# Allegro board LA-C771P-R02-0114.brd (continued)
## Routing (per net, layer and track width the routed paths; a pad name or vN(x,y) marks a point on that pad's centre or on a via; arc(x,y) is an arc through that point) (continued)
ICLK_RCOMP: length 2
  TOP w0.254: v3(108.64,84.84) 108.21,84.41 RC31.2
  BOTTOM w0.254: UC4.AD13 108.92,84.61 108.88,84.61 v3(108.64,84.84)
ICLK_USB_TERMN: length 4.7
  TOP w0.102: RC57.2 98.86,83.75 98.86,84.36 98.48,84.74 v4(98.48,85.05) 98.48,85.32 98.76,85.6 99.35,85.6 99.57,85.83 99.57,86.13 v3(99.75,86.3)
  BOTTOM w0.102: v3(99.75,86.3) 100.19,85.86 UC4.F10
ICLK_USB_TERMP: length 4.7
  TOP w0.102: v3(99.13,86.3) 99.35,86.08 99.35,85.93 99.25,85.83 98.67,85.83 98.25,85.42 98.25,84.64 98.63,84.26 98.63,83.8 RC56.2
  BOTTOM w0.102: v3(99.13,86.3) 99.48,85.95 UC4.D10
ILB_RTC_EXTPAD: length 7.6
  BOTTOM w0.102: CC17.1 94.39,91.4 v2(94.78,91.01) 96.14,89.65 96.14,87.92 97.44,86.62 98.34,86.62 UC4.B8
ILB_RTC_X1: length 11.4
  BOTTOM w0.102: YC2.2 91.19,90.3 CC19.1 93.35,90.3 RC42.2 94.01,89.65 94.34,89.65 v2(94.7,89.29) 95.01,88.98 95.01,86.76 95.85,85.91 97.98,85.91 98.12,86.06 98.21,86.15 UC4.C9
ILB_RTC_X2: length 11.1
  BOTTOM w0.102: UC4.A9 96.09,86.29 v2(95.54,86.84) 95.46,86.91 95.46,89.39 94.04,90.81 RC42.1 93.38,91.19 CC18.1 91.72,91.19 YC2.1
INVT_PWM_SOC: length 73.9
  TOP w0.102: RPC1.7 80.18,76.09 80.71,76.62 81.32,76.62 UC7.4 81.41,76.29 81.01,76.29 80.3,75.58 80.3,74.71 v1(79.04,73.45) 73.93,68.34 67.71,68.34 67.56,68.49 65.52,68.49 64.8,69.21 63.55,69.21 61.64,71.12 61.64,76.55 59.57,78.62 57.25,78.62 56.01,77.38 53.47,77.38 53.08,77.77 v3(53.08,79.27)
  IN1 w0.127: v3(53.08,79.27) 52.77,79.58 52.77,85.42 50.07,88.12 50.07,88.12 49.51,88.68 v3(49.51,95.57)
  BOTTOM w0.102: JEDP1.8 57.9,97.52 57.13,96.76 54.71,96.76 53.46,95.51 52.46,95.51 52.23,95.28 49.79,95.28 v3(49.51,95.57)
ISOLATE#: length 3.7
  BOTTOM w0.102: UL1.20 38.7,68.95 v2(38.99,69.24) 39.26,69.51 RL3.1 40.14,68.53 RL2.2
KSI0: length 101.8
  TOP w0.102: UB1.55 65.05,17.37 65.33,17.66 v3(65.33,18.83) ; v3(51.47,57.51) 51.47,57.54 50.73,56.8 49.08,56.8 44,61.89 44,69.22 44.38,69.61 44.38,72.32 44.79,72.72 44.79,76.28 53.15,84.64 57.49,84.64 57.72,84.87 ; 57.72,84.87 59.65,86.8 JKB1.12 59.65,87.77 60.26,88.38 60.26,90.38 63.9,94.02 JKB2.12 ; 57.72,84.87 v1(57.72,84.87)
  IN2 w0.127: v3(51.47,57.51) 50.48,56.52 50.48,52.4 51.42,51.46 51.42,43.08 52.97,41.53 52.97,29.82 63.96,18.83 v3(65.33,18.83)
KSI1: length 117.9
  TOP w0.102: v3(56.29,55.15) 54.76,56.68 54.76,57.29 54.76,57.29 54.76,57.72 52.35,60.13 v1(50.72,60.13) 50.21,60.13 46.51,63.83 46.51,67.89 46.9,68.28 46.9,71 51.47,75.57 51.47,78.56 55.04,82.12 60.94,82.12 63.78,84.97 65.66,84.97 66.35,85.66 69.3,85.66 70.65,87.01 JKB1.1 70.65,87.96 70.11,88.5 68.47,88.5 67.62,89.35 67.62,91.44 68.01,91.83 73.58,91.83 73.92,92.17 73.92,92.49 74.9,93.47 JKB2.1 ; v3(68.99,20.05) 68.69,20.05 67.27,18.62 67.27,17.99 66.24,16.97 UB1.56
  IN2 w0.127: v3(56.29,55.15) 57.22,55.15 60.79,51.58 60.79,43.44 60.23,42.88 60.23,37.28 60.99,36.52 60.99,30.72 64.12,27.59 64.12,25.49 65.57,24.03 66.65,24.03 68.99,21.69 v3(68.99,20.05)
KSI2: length 104.8
  TOP w0.102: UB1.57 62.36,16.57 58.76,20.18 58.76,23.02 55.61,26.17 55.61,31.26 57.54,33.19 57.54,34.35 57.81,34.62 v3(57.81,34.63) ; v3(52.84,55.81) 52.84,57.38 51.82,58.4 49.64,58.4 44.91,63.13 44.91,68.85 45.3,69.23 45.3,71.94 45.7,72.34 45.7,75.9 53.53,83.72 60.27,83.72 63.65,87.1 JKB1.8 63.65,88.21 62.95,88.91 62.95,90.04 66.14,93.23 67.15,93.23 67.9,93.98 JKB2.8
  IN2 w0.127: v3(52.84,55.81) 53.22,55.81 55.58,53.45 55.58,45.6 56.93,44.25 56.93,36.72 57.31,36.33 57.31,35.12 57.81,34.62 v3(57.81,34.63)
KSI3: length 105.9
  TOP w0.102: UB1.58 62.13,16.17 v2(58.73,19.57) 58.48,19.82 58.48,22.97 55.38,26.07 55.38,31.36 57.31,33.29 57.31,34.82 v3(57.76,35.28) ; JKB2.9 66.9,93.6 66.78,93.48 66.07,93.48 62.65,90.06 JKB1.9 62.65,87.08 59.52,83.95 53.43,83.95 45.47,75.99 45.47,72.44 45.07,72.03 45.07,69.32 44.68,68.94 44.68,62.18 48.68,58.17 51.72,58.17 52.46,57.44 52.46,56.09 v3(52.15,55.78)
  IN2 w0.127: v3(57.76,35.28) 57.76,36.31 57.18,36.89 57.18,44.38 55.84,45.73 55.84,53.56 53.1,56.3 52.66,56.3 v3(52.15,55.78)
KSI4: length 111.6
  TOP w0.102: v3(56.4,52.56) 53.88,55.08 53.88,55.33 53.84,55.36 53.84,57.29 53.83,57.29 53.83,57.36 52.1,59.09 49.96,59.09 45.6,63.46 45.6,68.56 45.98,68.95 45.98,71.65 46.39,72.06 46.39,74.77 54.66,83.04 60.55,83.04 63.4,85.88 65.28,85.88 65.97,86.57 66.51,86.57 66.65,86.71 JKB1.5 66.65,88.22 66.71,88.27 66.71,91.81 67.9,93.01 70.15,93.01 70.9,93.76 JKB2.5 ; UB1.59 61.84,15.77 58.2,19.41 58.2,22.89 55.15,25.94 55.15,31.45 57.08,33.38 57.08,35.16 57.36,35.44 57.36,35.45 57.6,35.69 59.74,35.69 v3(59.81,35.62)
  IN2 w0.127: v3(56.4,52.56) 56.39,52.56 56.94,52.01 57.5,52.01 59.77,49.74 59.77,43.86 59.22,43.3 59.22,36.22 v3(59.81,35.62)
KSI5: length 106.9
  TOP w0.102: v3(56.61,35.31) 56.61,33.51 v2(55.61,32.51) 54.92,31.82 54.92,25.79 57.89,22.82 57.89,19.31 61.83,15.37 UB1.60 ; v3(54.88,53.15) 54.88,53.49 53.6,54.77 53.6,57.27 52.01,58.86 49.87,58.86 45.37,63.36 45.37,68.66 45.75,69.04 45.75,71.75 46.16,72.15 46.16,75.71 53.72,83.27 60.46,83.27 63.43,86.23 65.31,86.23 65.65,86.57 JKB1.6 65.65,88.43 65.82,88.6 65.82,91.25 67.8,93.24 69.36,93.24 69.9,93.77 JKB2.6
  IN2 w0.127: v3(54.88,53.15) 54.87,53.14 54.87,43.58 55.76,42.69 55.76,36.17 v3(56.61,35.31)
KSI6: length 114.2
  TOP w0.102: v3(56.83,54.06) 56.22,54.67 55.56,54.67 54.3,55.93 54.3,57.54 52.29,59.55 50.15,59.55 46.06,63.64 46.06,68.11 46.44,68.49 46.44,71.46 47.02,72.05 v2(47.02,73.1) 47.02,74.76 54.85,82.58 60.74,82.58 63.59,85.43 65.47,85.43 66.16,86.11 68.05,86.11 68.65,86.71 JKB1.3 68.65,87.68 67.16,89.16 67.16,91.62 67.9,92.36 71.53,92.36 72.9,93.73 JKB2.3 ; v3(67.75,18.47) 67.75,17.66 65.05,14.97 UB1.61
  IN2 w0.127: v3(67.75,18.47) 67.75,19.87 68.16,20.28 68.16,21.81 66.44,23.53 65.36,23.53 63.58,25.3 63.58,27.41 60.48,30.51 60.48,36.31 59.72,37.07 59.72,43.09 60.28,43.65 60.28,51.34 57.56,54.06 v3(56.83,54.06)
KSI7: length 117.5
  TOP w0.102: JKB2.2 73.9,93.02 73.67,92.79 73.67,92.65 73.67,92.64 73.67,92.31 73.67,92.31 73.67,92.24 73.49,92.05 67.92,92.05 67.39,91.53 67.39,89.26 68.38,88.27 69.07,88.27 69.65,87.7 JKB1.2 69.65,86.64 68.89,85.89 66.26,85.89 65.57,85.2 63.68,85.2 60.84,82.35 54.94,82.35 47.42,74.83 47.42,72.12 46.67,71.37 46.67,68.37 46.28,67.99 46.28,63.74 50.25,59.78 52.39,59.78 54.53,57.63 54.53,56.3 v2(54.78,56.05) v3(55.53,55.3) ; v3(68.38,18.45) 68.38,17.98 64.98,14.57 UB1.62
  IN2 w0.127: v3(55.53,55.3) 56.11,54.72 57.29,54.72 60.53,51.47 60.53,43.54 59.98,42.99 59.98,37.18 60.74,36.42 60.74,30.61 63.84,27.51 63.84,25.41 65.46,23.78 66.54,23.78 68.41,21.91 68.41,18.47 v3(68.38,18.45)
KSO0: length 97.1
  TOP w0.102: UB1.39 62.8,23.77 v3(62.76,23.73) ; JKB2.7 68.9,94.04 68.32,93.46 67.71,93.46 65.54,91.29 65.54,89.06 64.65,88.17 JKB1.7 64.65,86.97 64.14,86.46 63.33,86.46 60.36,83.49 53.62,83.49 45.93,75.8 45.93,72.25 45.52,71.84 45.52,69.14 45.14,68.75 45.14,63.23 49.74,58.63 51.91,58.63 53.37,57.17 53.37,54.28 v2(53.59,54.06) v3(54.21,53.45)
  IN2 w0.127: v3(54.21,53.45) 54.39,53.62 55.05,53.62 55.33,53.35 55.33,45.49 56.67,44.15 56.67,36.61 57.05,36.23 57.05,34.55 57.4,34.21 58.43,34.21 58.96,33.69 58.96,29.87 60,28.83 60,26.9 60.31,26.6 60.31,25.51 61.45,24.36 62.36,24.36 62.76,23.97 v3(62.76,23.73)
KSO1: length 110.6
  TOP w0.102: UB1.40 66.28,23.37 68.1,21.55 68.1,20.43 66.45,18.78 v3(66.45,17.96) ; JKB2.11 64.9,93.47 63.48,92.05 62.25,92.05 60.49,90.29 60.49,88.65 60.65,88.49 JKB1.11 60.65,86.4 v1(59.41,85.16) 58.65,84.41 53.24,84.41 45.02,76.18 45.02,72.63 44.61,72.22 44.61,69.51 44.22,69.13 44.22,61.99 49.18,57.03 50.36,57.03 v3(50.83,57.51)
  IN2 w0.127: v3(66.45,17.96) 66.05,18.37 64.06,18.37 52.71,29.72 52.71,41.42 51.16,42.97 51.16,51.36 50.22,52.29 50.22,56.9 v3(50.83,57.51)
KSO2: length 103.2
  TOP w0.102: UB1.41 61.62,22.97 60.26,24.34 60.26,35.85 59.93,36.18 57.62,36.18 57.19,35.75 56.42,35.75 54.19,33.51 v3(54.19,33.08) ; JKB2.13 62.9,93.94 60.03,91.07 60.03,89.85 58.65,88.47 JKB1.13 58.65,86.56 56.95,84.87 53.05,84.87 44.31,76.12 v2(44.31,74.33) 44.31,72.56 44.15,72.41 44.15,69.7 43.77,69.32 43.77,61.8 49.01,56.55 51.37,56.55 v3(51.98,57.16)
  IN2 w0.127: v3(54.19,33.08) 54.19,33.49 53.22,34.45 53.22,41.63 51.67,43.18 51.67,51.57 50.73,52.5 50.73,55.91 v3(51.98,57.16)
KSO3: length 92.6
  TOP w0.102: v3(53.85,51.8) 53.35,51.8 49.85,55.3 45.66,55.3 42.62,58.33 42.62,69.96 41.8,70.78 41.8,72.59 42.45,73.24 42.45,75.88 53.65,87.08 JKB1.18 53.65,88.3 54.14,88.78 54.14,89.54 57.9,93.31 JKB2.18 ; UB1.42 61.7,22.57 58.91,25.36 v2(58.91,28.3) 58.91,28.68 v3(58.53,29.06)
  IN2 w0.127: v3(53.85,51.8) 54.62,51.03 54.62,43.47 55.51,42.58 55.51,35.7 57.25,33.96 58.33,33.96 58.53,33.76 v3(58.53,29.06)
KSO4: length 98.4
  TOP w0.102: JKB2.14 61.9,93.88 60.36,92.34 59.04,92.34 57.31,90.6 57.31,88.57 57.65,88.23 JKB1.14 57.65,86.07 56.67,85.1 52.96,85.1 43.36,75.5 43.36,72.63 43.92,72.07 43.92,69.89 43.54,69.5 43.54,61.7 44.58,60.66 44.58,59.39 46.43,57.54 ; v2(46.44,57.54) 46.43,57.54 ; 46.43,57.54 47.77,56.21 50.82,56.21 54.07,52.96 54.48,52.96 55.5,51.94 v3(56.36,51.94) ; UB1.43 65.06,22.17 65.74,22.85 v3(66.07,22.85)
  IN2 w0.127: v3(66.07,22.85) 65.9,23.02 65.15,23.02 63.05,25.12 63.05,27.22 59.98,30.3 59.98,34.85 58.96,35.87 58.96,43.5 59.52,44.06 59.52,49.54 57.35,51.71 56.58,51.71 v3(56.36,51.94)
KSO5: length 108
  TOP w0.102: v3(49.96,57.52) v2(49.33,57.52) 49.01,57.52 44.45,62.08 44.45,69.03 44.84,69.42 44.84,72.13 45.25,72.53 45.25,76.09 53.34,84.18 59.06,84.18 61.65,86.77 JKB1.10 61.65,88.19 62.39,88.93 62.39,90.12 65.9,93.63 JKB2.10 ; UB1.44 65.23,21.77 65.89,22.43 66.84,22.43 67.87,21.4 67.87,20.53 65.82,18.47 v3(65.82,17.94)
  IN2 w0.127: v3(49.96,57.52) 49.94,57.51 49.94,52.21 50.91,51.25 50.91,42.87 52.46,41.32 52.46,29.56 64.08,17.94 v3(65.82,17.94)
KSO6: length 99.3
  TOP w0.102: v3(56.27,49.36) v2(56.27,50) 54.01,52.25 53.29,52.25 50.02,55.52 45.75,55.52 42.85,58.42 42.85,70.14 42.03,70.97 42.03,72.49 42.68,73.14 42.68,75.78 52.97,86.08 54.1,86.08 54.65,86.63 JKB1.17 54.65,88.91 58.9,93.16 JKB2.17 ; v3(66.73,21.05) 66.73,21.93 66.45,22.2 65.99,22.2 65.15,21.37 UB1.45
  IN2 w0.127: v3(56.27,49.36) 56.09,49.18 56.09,45.83 57.44,44.49 57.44,37 58.17,36.26 58.17,35.58 59.21,34.54 59.21,29.98 60.25,28.94 60.25,27.01 61.58,25.69 61.58,25.19 62.1,24.67 62.42,24.67 63.46,23.63 63.46,22.97 65.37,21.05 v3(66.73,21.05)
KSO7: length 99.1
  TOP w0.102: v3(66.2,21.8) 65.37,20.97 UB1.46 ; JKB2.15 60.9,93.66 59.95,92.72 59.1,92.72 57.06,90.67 57.06,88.53 56.65,88.12 JKB1.15 56.65,86.47 v2(55.8,85.62) 55.58,85.4 52.94,85.4 43.14,75.6 43.14,72.53 43.7,71.97 43.7,69.98 43.31,69.6 43.31,58.61 45.94,55.98 50.73,55.98 53.97,52.74 54.38,52.74 55.78,51.34 v3(56.32,51.34)
  IN2 w0.127: v3(66.2,21.8) 66.01,21.8 62.63,25.18 62.31,25.18 62.08,25.41 62.08,27.83 59.72,30.19 59.72,34.75 58.71,35.76 58.71,43.77 59.26,44.33 59.26,49.41 57.34,51.34 v3(56.32,51.34)
KSO8: length 100.3
  TOP w0.102: JKB2.16 59.9,93.84 55.65,89.59 JKB1.16 55.65,86.61 54.67,85.63 52.85,85.63 42.91,75.69 42.91,72.44 43.47,71.88 43.47,70.08 43.08,69.69 43.08,58.52 44.88,56.72 45.85,55.75 50.37,55.75 v2(51.31,54.82) 53.64,52.48 54.31,52.48 56.06,50.73 v3(56.29,50.73) ; UB1.47 67.08,20.57 v3(67.47,20.96)
  IN2 w0.127: v3(56.29,50.73) 56.29,50.68 56.76,50.21 56.76,48.79 56.4,48.42 56.4,45.89 57.69,44.59 57.69,37.1 58.43,36.37 58.43,35.68 59.47,34.64 59.47,30.09 60.51,29.04 60.51,27.11 61.83,25.79 61.83,25.3 62.21,24.92 62.52,24.92 64.58,22.86 64.58,22.29 65.51,21.37 66.45,21.37 66.55,21.47 66.96,21.47 v3(67.47,20.96)
KSO9: length 108.5
  TOP w0.102: JKB2.4 71.9,93.79 70.7,92.59 67.81,92.59 66.94,91.72 66.94,88.45 67.65,87.74 JKB1.4 67.65,86.85 67.14,86.34 66.07,86.34 65.38,85.65 63.49,85.65 60.65,82.81 54.75,82.81 46.64,74.7 46.64,71.99 46.21,71.56 46.21,68.59 45.83,68.2 45.83,63.55 50.06,59.32 52.2,59.32 54.07,57.44 54.07,55.6 v2(55.46,54.22) 56.02,54.22 v3(56.21,54.02) ; v3(66.88,20.16) 66.87,20.17 UB1.48
  IN2 w0.127: v3(56.21,54.02) 56.63,53.6 57.66,53.6 60.03,51.24 60.03,43.75 59.47,43.2 59.47,36.97 60.23,36.21 60.23,30.4 63.33,27.3 63.33,25.2 65.25,23.27 66.33,23.27 67.9,21.7 67.9,20.67 67.39,20.16 v3(66.88,20.16)
KSO10: length 93.3
  TOP w0.102: UB1.49 62.85,19.77 61.96,20.66 v2(61.96,21.09) 61.96,21.96 58.45,25.46 v3(58.45,27.01) ; JKB2.23 52.9,92.6 48.65,88.35 JKB1.23 48.65,86.78 48.27,86.39 47.25,86.39 40.42,79.56 40.42,70.22 40.65,69.99 40.65,58.33 45.08,53.9 48.37,53.9 52.18,50.1 v3(52.18,48.9)
  IN2 w0.127: v3(52.18,48.9) 52.18,48.83 53.04,47.96 53.04,42.89 53.98,41.95 53.98,34.97 55.15,33.8 55.15,33.03 56.83,31.35 56.83,27.95 57.77,27.01 v3(58.45,27.01)
KSO11: length 94.6
  TOP w0.102: UB1.50 62.54,19.37 61.35,20.56 61.35,22.24 58.05,25.54 v2(58.05,26.12) 58.05,27.31 v3(58.38,27.64) ; v3(52.99,48.7) 52.99,48.7 52.53,49.15 52.53,50.07 48.47,54.13 45.17,54.13 40.87,58.43 40.87,70.09 40.65,70.32 40.65,79.47 47.31,86.14 49.39,86.14 49.65,86.4 JKB1.22 49.65,88.49 53.37,92.21 53.37,92.85 53.9,93.37 JKB2.22
  IN2 w0.127: v3(52.99,48.7) 52.99,48.7 53.3,48.39 53.3,42.99 54.24,42.06 54.24,35.07 55.41,33.9 55.41,33.13 57.08,31.46 57.08,28.94 v3(58.38,27.64)
KSO12: length 96.6
  TOP w0.102: UB1.51 62.24,18.97 60.61,20.6 60.61,22.65 57.26,26.01 57.26,28.79 58.84,30.37 58.84,32.76 v3(58.07,33.54) ; v3(53.85,51.19) 53.64,51.19 49.78,55.05 45.55,55.05 42.4,58.2 42.4,69.86 41.56,70.7 41.56,72.79 41.89,73.12 v2(41.89,74.3) 41.89,75.65 52.65,86.4 JKB1.19 52.65,88.94 56.9,93.19 JKB2.19
  IN2 w0.127: v3(58.07,33.54) 57.31,33.54 55.25,35.6 55.25,42.48 54.36,43.37 54.36,50.68 v3(53.85,51.19)
KSO13: length 96.2
  TOP w0.102: v3(53.85,50.55) 49.58,54.82 45.45,54.82 42.17,58.11 42.17,69.77 41.33,70.6 41.33,75.41 51.65,85.73 JKB1.20 51.65,88.58 55.9,92.83 JKB2.20 ; UB1.52 62.29,18.57 59.95,20.91 v2(59.95,22.13) 59.95,22.99 57.16,25.78 57.03,25.91 57.03,28.88 58.4,30.25 58.4,31.61 v3(58.01,31.99)
  IN2 w0.127: v3(58.01,31.99) 57.62,31.99 56.17,33.45 56.17,34.22 55,35.39 55,42.37 54.07,43.3 54.07,50.33 v3(53.85,50.55)
KSO14: length 97.6
  TOP w0.102: UB1.53 62.23,18.17 59.52,20.88 59.52,22.97 56.8,25.68 56.8,29.34 v2(57.31,29.85) 57.86,30.4 v3(57.86,30.94) ; v3(53,49.92) 48.56,54.36 45.26,54.36 41.1,58.52 41.1,70.18 40.87,70.41 40.87,79.38 47.26,85.76 49.84,85.76 50.65,86.56 JKB1.21 50.65,88.72 51.34,89.42 52.16,89.42 54.9,92.15 JKB2.21
  IN2 w0.127: v3(57.86,30.94) 57.86,31.4 55.91,33.35 55.91,34.11 54.74,35.28 54.74,42.27 53.82,43.19 53.82,49.11 v3(53,49.92)
KSO15: length 94.5
  TOP w0.102: v3(52.16,48.25) 51.77,48.64 51.77,50.18 48.28,53.68 44.98,53.68 40.42,58.24 40.42,69.9 40.19,70.13 40.19,79.66 47.65,87.12 JKB1.24 47.65,87.76 51.9,92.01 JKB2.24 ; UB1.54 62.17,17.77 59.24,20.7 59.24,22.92 56.37,25.79 v2(56.37,27.95) 56.07,28.25 v3(56.07,30.94)
  IN2 w0.127: v3(52.16,48.25) 52.79,47.63 52.79,42.78 53.73,41.85 53.73,34.86 54.9,33.69 54.9,32.11 v3(56.07,30.94)
KSO16: length 107.4
  TOP w0.102: JKB2.25 50.9,93.29 50.33,92.72 50.33,91.73 47.59,89 46.89,89 46.16,88.26 46.16,86.44 39.96,80.24 39.96,70.03 40.19,69.81 40.19,58.14 44.89,53.45 48.18,53.45 51.09,50.54 v2(51.09,49.16) 51.09,48.7 v3(52.15,47.63) ; v3(72.22,18.39) 72.13,18.3 UB1.81
  IN2 w0.127: v3(72.22,18.39) 72.04,18.57 69.65,18.57 68.84,17.76 67.29,17.76 65.77,19.28 64.27,19.28 54.64,28.91 54.64,33.59 53.47,34.76 53.47,41.74 52.53,42.68 52.53,47.25 v3(52.15,47.63)
KSO17: length 109.6
  TOP w0.102: v3(45.09,52.76) 40.74,57.11 v2(40.64,57.11) 39.96,57.79 39.96,69.71 39.73,69.94 39.73,80.33 45.14,85.74 45.14,88.04 46.74,89.64 47.91,89.64 49.9,91.63 JKB2.26 ; UB1.82 72.53,17.61 v3(72.9,17.99)
  IN2 w0.127: v3(45.09,52.76) 45.5,52.35 49.44,52.35 50.65,51.14 50.65,42.76 52.2,41.21 52.2,29.45 64.15,17.51 68.94,17.51 69.76,18.32 71.48,18.32 71.86,17.94 72.85,17.94 v3(72.9,17.99)
LAN_CLKREQ#: length 128.4
  TOP w0.102: v3(77.81,95.49) 80.07,95.49 80.45,95.87 89.59,95.87 93.53,99.81 103.39,99.81 104.58,101 119.67,101 122.05,98.61 122.05,97.7 122.54,97.21 122.54,95.82 122.97,95.38 RPC3.1 123.35,95 123.23,94.88 122.69,94.88 122.52,95.04 CC95.1 122.05,93.88 120.89,92.71 118.9,92.71 v3(118.75,92.57)
  IN2 w0.127: v3(77.81,95.49) 76.89,96.4 56.55,96.4 55.86,95.72 51.21,95.72 50.53,96.4 47.05,96.4 34.37,83.72 v3(34.37,73.09)
  BOTTOM w0.089: UC4.BG5 119.71,88.03 119.24,88.5 118.65,88.5 118.12,89.04 117.89,89.04 117.72,89.21 117.72,89.26 117.71,89.26 117.71,89.5 117.72,89.5
  BOTTOM w0.102: v3(34.37,73.09) 34.37,72.99 35.22,72.13 35.22,72.03 35.47,71.79 UL1.12 ; 117.72,89.5 117.72,89.63 117.81,89.72 117.81,90.81 118.25,91.25 118.5,91.25 118.86,91.61 118.86,92.11 118.75,92.21 v3(118.75,92.57)
LAN_MDIN0: length 13.5
  BOTTOM w0.102: TL1.7 27.43,62.47 27.71,62.19 28.41,62.19 28.86,62.64 28.86,64.79 v4(28.86,64.8) 28.86,64.8 28.86,65.24 28.71,65.39 28.71,66.79 29.07,67.14 30.52,67.14 31.22,66.44 DL2.1 31.22,66.05 31.35,65.92 31.87,65.92 32.39,66.45 32.39,67.18 32.96,67.75 UL1.2
LAN_MDIN1: length 9.9
  BOTTOM w0.102: UL1.5 32.02,68.95 31.68,68.62 31.68,68.4 31.51,68.23 31.36,68.23 31.22,68.37 DL2.6 31.22,69.72 31.07,69.87 30.83,69.87 30.37,70.33 v4(29.54,70.33) 29.14,70.33 28.15,69.34 28.04,69.34 27.9,69.48 27.9,69.94 27.74,70.09 TL1.1
LAN_MDIP0: length 13.5
  BOTTOM w0.102: UL1.1 33.14,67.35 32.8,67.01 32.8,66.28 32.04,65.52 31.63,65.52 31.17,65.06 30.31,65.06 29.73,65.64 29.73,66.02 DL2.3 29.12,66.21 29.12,65.57 29.27,65.41 29.27,63.17 v4(29.27,63.17) 29.27,63.17 29.27,62.47 28.58,61.78 27.85,61.78 27.26,61.2 TL1.8
LAN_MDIP1: length 9.9
  BOTTOM w0.102: TL1.2 27.85,68.82 27.96,68.93 28.32,68.93 29.27,69.88 29.84,69.88 29.94,69.78 29.94,69.66 29.32,69.05 DL2.4 29.32,68.83 30.32,67.83 31.68,67.83 32.09,68.23 32.09,68.45 32.18,68.55 v4(32.49,68.55) 33.62,68.55 UL1.4
LANGND:
  vias: v2(17.77,74.38) v3(14.89,61.62) v3(15,62.51) v3(16.76,73.77) v3(17.35,73.84)
LDO1: length 6.6
  TOP w0.203: CA16.2 21.86,20.33 22.81,20.33 23.3,20.83 23.3,20.97 23.37,21.04 UA1.27
  TOP w0.254: RA14.2 19.9,18.56 v3(19.91,18.56) 19.91,18.59 21.34,20.02 CA16.2
  BOTTOM w0.102: v2(19.74,19.29) 19.74,18.73 v3(19.91,18.56)
LDO2: length 3.6
  TOP w0.102: v3(29.4,22.16) 29.42,22.13 v2(29.42,21.6)
  TOP w0.203: v3(29.4,22.16) 29.24,22.31 29.24,22.73 28.9,23.08 UA1.39
  BOTTOM w0.254: CA13.2 v3(29.4,22.16)
LDO3: length 3.9
  TOP w0.102: UA1.7 24.57,28.36 25.38,29.17 25.97,29.17 v2(25.99,29.19) 26.75,29.95 CA12.2
LED1_GPIO: length 5.8
  BOTTOM w0.102: UL1.26 36.67,66.21 37.44,65.44 38.11,65.44 38.72,64.83 RL4.1 39.94,62.94 v2(39.94,62.7)
LG_DDR: length 0.7
  TOP w0.102: v3(152.34,29.73) 152.59,29.98 v2(152.89,29.98)
  vias: v3(148.17,28.71) v3(148.16,28.1) v3(152.34,29.09)
LGATE1: length 12.4
  IN2 w0.762: 156.05,76.97 156.58,76.97 157.44,76.11 157.44,71.51 155.76,69.83 155.76,68.58 155.45,68.26 155.45,66.27
  vias: v3(155.05,77.37) v3(155.41,65.64) v3(155.4,64.98) v3(155.61,77.58)
LGATEG: length 15.2
  IN2 w0.762: 158.68,80.25 158.86,80.07 158.86,74.23 159.34,73.75 159.34,69.43 157.1,67.18 157.1,66.28
  vias: v3(157.03,65.1) v3(157.38,79.68) v3(157.44,65.6) v3(157.97,79.69)
LID_SW#: length 119.3
  TOP w0.102: v2(24.79,92.21) 25.61,91.4 C11.1 ; v3(70.36,25) 72.2,25 74.11,23.08 74.11,22.22 74.69,21.65 77.5,21.65 78.18,20.97 79.75,20.97 UB1.115 82.26,20.97 RB5.1 ; C11.1 26.86,90.73 26.86,89.63 27.57,88.92 D2.3 27.57,87.59 27.56,87.59 v3(27.56,86.52) ; C11.1 26.2,94.58 26.88,95.26 31.7,95.26 31.98,94.98 JPWRB1.6
  IN2 w0.127: v3(54.26,61.3) 55.76,59.8 55.76,57.59 61.58,51.77 61.58,43.33 60.87,42.62 60.87,39.35 63.13,37.09 63.13,33.38 63.91,32.6 63.91,32.03 70.36,25.58 v3(70.36,25)
  BOTTOM w0.102: v3(27.56,86.52) 28.02,86.06 28.02,80.32 34.93,73.41 39.15,73.41 39.79,72.77 42.81,72.77 44.15,71.43 44.15,66.33 45.78,64.7 49.96,64.7 53.37,61.3 v3(54.26,61.3)
LINE1-L: length 2.1
  TOP w0.203: v3(20.58,22.61) 20.73,22.61 21.19,23.07 21.48,23.07 21.49,23.08 UA1.22
  BOTTOM w0.203: v3(20.58,22.61) 20.48,22.51 CA23.2
LINE1-R: length 3.5
  TOP w0.203: v3(20.56,23.2) 20.67,23.31 20.95,23.31 21.11,23.48 UA1.21
  BOTTOM w0.203: v3(20.56,23.2) 19.92,23.2 v2(19.65,22.93) 19.21,22.49 CA24.2
LINE2-L:
  vias: v2(20.66,21.11)
LINE2-MIC: length 60.4
  IN1 w1.016: 26.53,76.56 28.4,74.68 28.4,54.65 23.55,49.8 23.55,36.17 19.41,32.03 19.41,26.81 18.68,26.07 18.68,24.16 18.5,23.98 18.5,21.07
  vias: v2(24.11,77.38) v3(18.02,20) v3(18.68,20) v3(24.48,18.29) v3(24.98,17.98) v3(25.05,76.95) v3(25.05,76.18)
LINE2-R: length 2.7
  TOP w0.203: UA1.23 21.3,22.68 20.71,22.08 20.28,22.08 19.79,22.56 RA32.2
LPC_AD0: length 192.2
  TOP w0.102: v3(94.75,23.83) 94.38,23.47 94.38,22.52 93.45,21.6 UW1.26 ; UB1.10 74.53,25.49 v3(74.63,25.38)
  BOTTOM w0.102: v3(74.63,25.38) 75.27,24.74 85.38,24.74 86.93,23.2 94.11,23.2 v3(94.75,23.83) 100.44,23.83 100.79,23.48 120.7,23.48 129.76,14.41 160.05,14.41 161.68,16.04 161.68,41.28 v2(153.36,49.6) 152.22,50.73 143.12,50.73 136.62,57.23 135.32,57.23 130.92,61.63 130.92,67.21 132.27,68.55 132.27,72.67 130.94,73.99 130.94,76.98 128.4,79.52 128.4,80.11 127.17,81.34 124.77,81.34 123.36,82.75 121.75,82.75 121.72,82.78 121.71,82.78 121.7,82.8 121.08,82.8 UC4.BH16
LPC_AD1: length 178.1
  TOP w0.102: v3(75.47,25.53) 75.33,25.68 UB1.8 ; UW1.23 92.24,23.55 v3(91.57,24.22)
  BOTTOM w0.102: UC4.BJ17 122.3,82.31 122.31,82.31 123.22,82.31 123.98,81.54 123.98,80.9 124.52,80.37 126.77,80.37 127.44,79.71 127.44,79.12 129.65,76.91 129.65,74.96 129.64,74.96 129.64,73.92 130.84,72.72 130.84,68.5 129.47,67.12 129.47,65.16 129.95,64.68 129.95,61.23 134.92,56.27 136.22,56.27 142.72,49.77 v2(144.58,49.77) 151.82,49.77 160.23,41.36 160.23,24.92 154.69,19.38 126.33,19.38 121.26,24.44 101.43,24.44 100.41,25.46 97.8,25.46 97.19,24.85 93.68,24.85 93.05,24.22 v3(91.57,24.22) 91.09,24.7 88.45,24.7 86.85,26.3 76.3,26.3 75.56,25.56 75.49,25.56 v3(75.47,25.53)
LPC_AD2: length 204.6
  TOP w0.102: v3(75.98,23.63) 75.98,25.91 75.73,26.17 UB1.7 ; UW1.20 94.43,25.5 95.59,24.34 v3(95.59,21.8)
  BOTTOM w0.102: v3(75.98,23.63) 76.96,22.64 81.98,22.64 82.92,21.7 88.22,21.7 89.39,20.53 94.17,20.53 95.45,21.8 v3(95.59,21.8) 96.08,21.31 101.41,21.31 101.66,21.55 119.9,21.55 128.99,12.45 160.83,12.45 163.61,15.24 163.61,42.85 159.41,47.05 158.64,47.05 153.02,52.66 152.37,52.66 150.95,54.09 148.93,54.09 144.33,58.68 v2(144.33,59.65) 144.33,65.01 140.5,68.84 140.09,68.84 139.33,69.6 136.18,69.6 135.8,69.22 134.53,69.22 134.2,69.55 134.2,73.47 133.41,74.25 133.41,83.88 131.86,85.43 124.64,85.43 124.16,84.94 123.17,84.94 122.7,84.48 121.69,84.48 UC4.BJ13
LPC_AD3: length 207.2
  TOP w0.102: UB1.5 76.53,23.86 v3(76.66,23.73) ; v3(96.27,21.82) 96.27,24.67 94.39,26.55 94.39,27.06 94.01,27.45 UW1.17
  BOTTOM w0.102: v3(76.66,23.73) 77.26,23.12 82.18,23.12 83.12,22.18 89.32,22.18 90.49,21.01 93.97,21.01 95.27,22.31 95.78,22.31 v3(96.27,21.82) 101.25,21.82 101.46,22.03 120.1,22.03 129.19,12.94 160.63,12.94 163.12,15.44 163.12,42.65 159.21,46.57 158.44,46.57 152.82,52.18 152.17,52.18 150.75,53.6 142.49,53.6 v2(140.23,55.87) 137.42,58.68 135.92,58.68 132.37,62.24 132.37,66.53 133.71,67.88 133.71,73.27 132.92,74.05 132.92,83.68 131.66,84.94 124.64,84.94 124.3,84.6 123.5,84.6 123.14,84.23 121.89,84.23 121.63,83.97 121.3,83.97 121.18,84.09 120.98,84.09 120.66,83.77 UC4.BG14
LPC_CLK_0: length 8.4
  TOP w0.102: v2(123.91,84.14) v3(123.22,83.46)
  BOTTOM w0.102: UC4.BG15 120.9,83.46 121.19,83.46 121.3,83.57 121.83,83.57 122.02,83.76 122.53,83.76 122.83,83.46 v3(123.22,83.46) 124.32,83.46 124.53,83.24 CC27.1 125.24,82.79 126.98,82.79 RC66.2
LPC_CLK_1: length 6.8
  BOTTOM w0.102: RC67.2 126.84,83.72 125.24,83.72 CC28.1 v2(123.78,84.18) 123.64,84.18 123.44,83.98 121.92,83.98 121.71,83.77 121.08,83.77 UC4.BH14
LPC_CLK_EC: length 188.4
  TOP w0.102: v3(73.73,25.46) UB1.12
  BOTTOM w0.102: RC66.1 128.8,83.69 131.36,83.69 131.94,83.12 131.94,73.68 132.75,72.87 132.75,68.35 131.4,67.01 131.4,61.83 135.52,57.71 137.02,57.71 142.09,52.64 v2(143.34,52.64) 150.35,52.64 151.77,51.22 152.42,51.22 158.04,45.6 158.81,45.6 162.16,42.25 162.16,15.84 160.23,13.9 129.59,13.9 120.5,23 100.56,23 100.28,23.28 94.87,23.28 94.26,22.66 83.32,22.66 82.38,23.61 80.2,23.61 79.54,24.26 74.92,24.26 v3(73.73,25.46)
LPC_CLK_TCM: length 173.5
  TOP w0.102: RW2.2 89.47,22.49 89.86,22.1 v3(90.58,22.1)
  BOTTOM w0.102: RC67.1 131.56,84.18 132.44,83.3 132.44,73.85 133.23,73.07 133.23,68.15 131.88,66.81 131.88,62.03 135.72,58.2 137.22,58.2 142.29,53.12 v2(146.64,53.12) 150.55,53.12 151.97,51.7 152.62,51.7 158.24,46.08 159.01,46.08 162.64,42.45 162.64,15.64 160.43,13.42 129.39,13.42 120.3,22.51 100.36,22.51 100.08,22.79 95.07,22.79 93.9,21.62 91.06,21.62 v3(90.58,22.1)
LPC_CLKRUN#: length 8.9
  TOP w0.102: v3(123.99,83.07) 124.65,82.41 v2(124.75,82.41)
  BOTTOM w0.102: UC4.BG16 120.66,82.79 120.96,83.1 121.21,83.1 121.3,83 121.35,83 121.35,83 121.78,83 121.84,82.95 123.38,82.95 123.49,83.07 v3(123.99,83.07) 124.75,82.3 RC68.1 125.24,81.87 126.82,81.87 126.82,81.87 127.11,81.87 RC82.1
LPC_FRAME#: length 177.9
  TOP w0.102: UW1.22 93.83,24.2 v3(93.91,24.11) ; UB1.4 76.93,25.87 v3(77.01,25.78)
  BOTTOM w0.102: UC4.BG17 121.01,82.31 121.29,82.59 121.62,82.59 121.63,82.58 121.63,82.58 121.67,82.54 123.28,82.54 124.24,81.58 124.24,81.19 124.57,80.85 126.97,80.85 127.92,79.91 127.92,79.32 130.13,77.11 130.13,74.76 130.13,74.76 130.13,74.42 130.13,74.41 130.13,74.12 131.78,72.46 131.78,68.75 130.44,67.41 130.44,61.43 135.12,56.75 136.42,56.75 142.92,50.25 v2(148.5,50.25) 152.02,50.25 160.71,41.56 160.71,24.72 154.89,18.9 125.96,18.9 120.9,23.96 101.23,23.96 100.21,24.98 98,24.98 97.39,24.36 94.16,24.36 v3(93.91,24.11) 93.48,23.68 87.21,23.68 85.55,25.33 77.46,25.33 v3(77.01,25.78)
LPC_RCOMP: length 4.1
  TOP w0.254: v3(119.54,82.31) 119.54,82.58 RC65.2 120.23,83.27 121.17,84.21 v2(122.11,84.21)
  BOTTOM w0.254: UC4.BF18 119.79,82.06 v3(119.54,82.31)
LX_1.05V:
  vias: v2(66.12,64.45)
LX_3V: length 3.9
  TOP w0.102: v3(193.58,38.74) v2(193.58,39.4)
  IN2 w0.508: 188.91,38.73 192.15,38.73
  vias: v3(187.63,39.73) v3(187.64,38.71) v3(192.94,38.74)
LX_5V: length 6.2
  IN2 w0.508: 44.82,46.25 44.82,49.05 45.45,49.68 47.23,49.68
  BOTTOM w0.102: v3(48.27,50.73) v2(48.27,51.47)
  vias: v3(44.87,45.25) v3(44.86,44.61) v3(47.61,50.72)
LX_CHG: length 0.7
  TOP w0.102: v2(196.27,71.64) 196.72,72.08 v3(196.82,72.08)
  vias: v3(191.8,69.73) v3(191.8,69.03) v3(191.8,68.33) v3(192.5,69.73) v3(192.5,69.03) v3(192.5,68.33) v3(192.65,71.32) v3(192.69,70.67) v3(197.42,72.08)
LX_DDR: length 1.5
  BOTTOM w0.102: 151.07,28.2 151.07,26.92 v2(151.24,26.76)
  vias: v3(145.07,32.8) v3(145.47,32.24) v3(145.73,32.85) v3(146.13,32.19) v3(146.44,32.85) v3(146.85,32.19) v3(147.1,32.85) v3(147.5,32.19) v3(147.78,32.85) v3(148.14,32.19) v3(148.15,30.23) v3(148.15,29.48) v3(148.45,32.83) v3(148.78,32.22) v3(148.8,29.5) v3(148.85,30.26) v3(150.62,30.23) v3(151.26,30.23)
ME_EN: length 174.9
  TOP w0.102: v3(124.92,71.61) 125.64,70.89 125.64,68.41 127.19,66.86 127.19,62.54 137.97,51.75 139.94,51.75 141.83,49.86 v3(141.83,44.88) ; v3(103.36,29.35) 103.36,8.57 99.75,4.96 98.28,4.96 93.73,9.51 92.67,9.51 88.66,13.52 82.08,13.52 81.03,14.57 UB1.99
  BOTTOM w0.102: v3(141.83,44.88) 142.5,44.2 150.32,44.2 v2(151.41,43.12) 157.33,37.19 157.33,26.12 153.88,22.67 151.82,22.67 151.3,23.19 127.38,23.19 121.65,28.91 103.79,28.91 v3(103.36,29.35) ; v3(124.92,71.61) 125.22,71.9 QC1.2 125.88,72.53 RC23.1
NOVO#: length 96.8
  TOP w0.102: v3(60.66,6.4) 61.91,7.65 61.91,9.61 v2(62.72,10.42) 62.89,10.6 64.17,10.6 65.18,11.61 65.18,12.77 66.3,13.89 66.78,13.89 69.45,16.57 69.45,20.28 68.79,20.94 68.79,22.23 66.2,24.82 66.2,25.59 66.02,25.77 UB1.34 ; v3(10.19,10.8) R16.1 9.84,11.54 7.2,8.9 D4.2 5.77,9.89 SW5.1 3.67,9.89 3.16,9.38 3.16,8.06 3.77,7.44 SW5.3
  IN2 w0.127: v3(60.66,6.4) 56.86,6.4 53.8,9.46 44.38,9.46 42.22,11.62 39.38,11.62 34.45,6.69 31.81,6.69 30.89,7.6 23.25,7.6 22.26,6.61 15.78,6.61 12.07,10.32 10.68,10.32 v3(10.19,10.8)
NTC: length 4.7
  TOP w0.102: v3(154.36,59.17) 153.63,58.43 153.63,57.69 v2(153.17,57.24)
  BOTTOM w0.203: PR723.1 154.11,58.91 v3(154.36,59.17) 154.49,59.17 154.85,59.53 PU602.7
NTC_1: length 32.3
  TOP w0.203: PH704.1 v3(153.41,77.9)
  IN1 w0.203: v3(153.41,77.9) 153.76,77.9 153.94,77.73 153.94,76.57 153.37,76 153.37,73.62 150.45,70.7 150.45,69.17 147.38,66.1 147.38,58.63 149.21,56.8 150.38,56.8 150.71,57.13 152.51,57.13 153.22,56.42 v3(153.22,56.17)
  BOTTOM w0.203: v3(153.22,56.17) PR727.1 PR723.2
NTCG: length 2.8
  BOTTOM w0.203: PU602.1 157.25,59.86 157.72,59.39 158,59.39 158.97,58.42 PR716.2
NTCG_1: length 52.9
  TOP w0.203: v3(162.47,56.42) 161.09,56.42 157.53,59.99 PR715.2
  TOP w0.254: v3(165.34,82.83) 164.02,82.83 162.45,84.39 156.83,84.39 PH703.2
  IN2 w0.254: v3(162.47,56.42) 162.97,56.42 168.1,61.55 168.1,80.06 v3(165.34,82.83)
  BOTTOM w0.203: v3(162.47,56.42) 162.47,55.99 162.19,55.71 159.49,55.71 v2(159.28,55.93) 158.97,56.24 PR716.1
NUVOTON_VTT: length 6.2
  TOP w0.203: UB1.117 81.35,21.77 v3(81.35,21.77)
  TOP w0.254: v3(81.35,21.77) 82.26,22.68 RB32.1 83.24,21.97 83.64,21.97 RB23.1
  BOTTOM w0.102: v3(81.35,21.77) v2(80.69,21.77)
ODD_DETECT#_R: length 3.4
  TOP w0.102: JODD1.8 225.43,106.65 226.21,105.88 v2(226.21,105.44) 226.21,104.67 RO5.2
ON/OFF#: length 113.4
  TOP w0.102: v3(71.01,24.59) 72.28,24.59 73.89,22.99 73.89,22.13 74.59,21.42 77.4,21.42 78.25,20.57 79.75,20.57 UB1.114 ; v3(28.68,87.12) 29.26,87.12 29.5,87.36 29.5,87.87 28.99,88.38 28.53,88.38 27.15,89.76 27.15,90.77 C10.1 R3.1 28.79,91.32 J2.2 29.98,91.39 JPWRB1.4 ; v3(55.07,61.32) 55.07,61.07 v2(54.79,60.78)
  IN2 w0.127: v3(71.01,24.59) 70.8,24.81 70.8,25.51 64.17,32.14 64.17,32.7 63.38,33.49 63.38,37.37 61.25,39.51 61.25,42.64 61.83,43.22 61.83,51.88 61.63,52.08 61.63,52.13 56.04,57.72 56.04,60.08 55.07,61.04 v3(55.07,61.32)
  BOTTOM w0.102: J1.2 28.33,87.47 v3(28.68,87.12) 29.34,86.46 29.34,79.33 35.03,73.64 39.24,73.64 39.88,73 42.91,73 44.38,71.53 44.38,66.48 45.93,64.93 50.06,64.93 53.23,61.76 54.64,61.76 v3(55.07,61.32)
P3: length 0.8
  BOTTOM w0.102: 46.15,82.18 v2(46.15,81.43)
PBTN_OUT#: length 117.8
  TOP w0.102: v3(85.96,33.23) v1(85.35,32.62) 84.83,32.1 84.83,28.68 85.07,28.43 85.07,26.53 85.43,26.18 85.43,25.35 84.75,24.67 84.14,24.67 83.73,24.26 82.03,24.26 81.37,23.61 80.88,23.61 80.72,23.77 UB1.122 ; RPC5.4 98.28,77.73 99.17,78.62 100.08,78.62 100.34,78.88 100.78,78.88 v3(101.26,78.4)
  IN2 w0.102: 99.75,78.85 97.34,81.26 96.23,81.26 95.74,81.74 95.28,81.74
  IN2 w0.127: 95.28,81.74 89.82,81.74 86.57,78.49 79.15,78.49 78.78,78.87 76.45,78.87 v3(76.08,78.5) ; v3(101.26,78.4) 100.81,78.85 99.75,78.85
  BOTTOM w0.102: UC4.J26 101.26,78.28 v3(101.26,78.4) ; v3(85.96,33.23) 85.04,33.23 82.76,35.52 71.64,35.52 70.55,36.61 67.07,36.61 64.78,38.9 64.78,40.37 63.82,41.33 63.82,43.41 65.08,44.68 65.08,45.83 66.01,46.76 66.01,48.15 74.33,56.46 74.33,74.14 73.8,74.66 73.8,75.77 76.08,78.05 v3(76.08,78.5)
PC_BEEP: length 2.2
  TOP w0.102: v3(22.02,28.38) 22.02,28.21 22.57,27.66 UA1.12
  BOTTOM w0.102: v3(22.02,28.38) 21.96,28.44 CA31.2
PCH_USB3_RX0_N: length 109.9
  IN2 w0.127: v3(27.68,47.14) 27.82,47.29 27.82,47.81 30.04,50.03 30.04,51.99 34.13,56.08 34.13,60.7 34.53,61.1 34.53,62.72 35.19,63.38 39.66,63.38 45.04,68.76 45.04,81.84 48.67,85.48 69.83,85.48 70.42,84.88 71.57,84.88 72.48,83.96 84.95,83.96 89.9,88.91 92.51,88.91 92.74,89.14 96.02,89.14 96.41,89.53 99.06,89.53 100.04,88.55 v3(100.13,88.55)
  BOTTOM w0.102: LS2.4 24.01,47.64 24.18,47.8 27.81,47.8 27.94,47.66 27.94,47.41 v3(27.68,47.14) ; v3(100.13,88.55) 100.07,88.61 UC4.E3
PCH_USB3_RX0_P: length 110
  IN2 w0.127: v3(99.67,88.09) 99.67,88.54 98.95,89.26 96.52,89.26 96.13,88.87 92.85,88.87 92.62,88.64 90.01,88.64 85.06,83.7 72.37,83.7 71.46,84.61 70.31,84.61 69.71,85.21 48.78,85.21 45.31,81.73 45.31,68.65 39.77,63.11 35.3,63.11 34.8,62.61 34.8,60.99 34.4,60.59 34.4,55.97 30.31,51.88 30.31,49.92 28.09,47.7 28.09,47.37 28.31,47.14 v3(28.42,47.14)
  BOTTOM w0.102: v3(99.67,88.09) 99.78,88.2 99.78,88.38 99.54,88.61 UC4.D4 ; LS2.1 24.04,48.14 24.16,48.01 27.9,48.01 28.16,47.75 28.16,47.41 v3(28.42,47.14)
PCH_USB3_TX0_N: length 114.6
  IN2 w0.127: v3(101.81,87.61) 101.59,87.83 101.45,87.83 101.2,88.07 101.2,89.19 100.27,90.12 98.14,90.12 94.5,93.76 89.59,93.76 89.17,93.35 89.17,90.98 87.76,89.57 87.76,87.64 84.6,84.47 72.69,84.47 71.18,85.98 47.93,85.98 44.52,82.57 44.52,68.96 39.45,63.89 34.96,63.89 33.48,62.41 33.48,57.06 28.96,52.54 28.96,52.05 29.16,51.85 29.33,51.85 29.49,52.01 v3(29.49,52.13)
  BOTTOM w0.102: v3(101.81,87.61) 102.22,87.2 UC4.K7 ; v3(29.49,52.13) 29.8,51.81 30.35,51.81 30.64,51.52 30.64,50.17 30.01,49.54 29.57,49.54 CS2.2
PCH_USB3_TX0_N_C: length 4.6
  BOTTOM w0.102: LS1.4 24.09,49.4 24.19,49.5 v4(26.85,49.5) 27.88,49.5 CS2.1
PCH_USB3_TX0_P: length 114.6
  IN2 w0.127: v3(101.88,88.29) 101.68,88.1 101.56,88.1 101.47,88.18 101.47,89.3 100.38,90.39 98.25,90.39 94.61,94.03 89.48,94.03 88.91,93.46 88.91,91.09 87.5,89.68 87.5,87.75 84.49,84.74 72.8,84.74 71.29,86.25 47.82,86.25 44.25,82.68 44.25,69.07 39.34,64.15 34.85,64.15 33.22,62.52 33.22,57.17 28.7,52.65 28.7,51.94 29.05,51.58 29.29,51.58 v3(29.49,51.38)
  BOTTOM w0.102: v3(101.88,88.29) 102.26,87.91 UC4.K6 ; CS1.2 29.57,49.76 29.92,49.76 30.42,50.26 30.42,51.43 30.26,51.6 29.7,51.6 v3(29.49,51.38)
PCH_USB3_TX0_P_C: length 4.7
  BOTTOM w0.102: CS1.1 27.81,49.72 v4(25.43,49.72) 24.29,49.72 24.1,49.9 LS1.1
PCIE_ATX_C_GRX_N0: length 109.5
  IN2 w0.127: v3(74.38,95.28) 73.87,95.28 73.73,95.14 70.3,95.14 70.04,94.88 47.5,94.88 36.01,83.39 36.01,72.59 v3(36.41,72.19)
  BOTTOM w0.102: v3(36.41,72.19) 36.18,71.95 36.18,71.26 36.27,71.17 UL1.14 ; v3(74.38,95.28) 74.38,95.72 75.12,96.45 85.71,96.45 89.55,100.3 114.6,100.3 115.37,99.52 118.42,99.52 119.11,98.83 119.11,95.74 118.48,95.12 118.19,95.12 117.93,94.85 117.93,94.48 117.84,94.39 CC9.2
PCIE_ATX_C_GRX_P0: length 109.5
  IN2 w0.127: v3(35.67,72.19) 35.75,72.26 35.75,83.5 47.39,95.14 69.92,95.14 70.19,95.41 73.62,95.41 v3(73.97,95.77)
  BOTTOM w0.102: CC8.2 118.14,94.64 118.14,94.76 118.28,94.9 118.57,94.9 119.32,95.65 119.32,98.92 118.51,99.74 115.46,99.74 114.69,100.51 89.46,100.51 85.62,96.67 75.03,96.67 74.12,95.77 v3(73.97,95.77) ; v3(35.67,72.19) 35.96,71.9 35.96,71.28 35.87,71.19 UL1.13
PCIE_GTX_C_ARX_N0: length 100
  IN2 w0.089: 108.54,88.23 108.56,88.21 108.56,88.16 109.25,87.46 109.25,86.81 110.03,86.04 110.03,84.84 110.49,84.38 112.93,84.38 114.09,85.54 114.34,85.54 v3(114.51,85.71)
  IN2 w0.127: v3(42.88,70.87) 42.72,71.04 42.29,71.04 41.78,71.55 41.78,82.45 48.63,89.29 52.48,89.29 53.39,90.19 55.67,90.19 57.08,91.6 65.46,91.6 65.85,91.21 67.1,91.21 68.07,90.24 76.09,90.24 79.97,94.12 85.5,94.12 87.45,96.07 95.74,96.07 97.62,94.19 98.31,94.19 100.27,92.22 102.53,92.22 104.48,90.27 106.5,90.27 108.54,88.23
  BOTTOM w0.102: UC4.AP10 114.08,85.71 114.51,85.71 v3(114.51,85.71) ; v3(42.88,70.87) 42.63,71.13 42.29,71.13 CL12.2
PCIE_GTX_C_ARX_P0: length 100
  IN2 w0.089: 108.35,88.04 108.37,88.02 108.42,88.03 109.06,87.38 109.06,86.73 109.84,85.96 109.84,84.76 110.41,84.19 113.01,84.19 114.17,85.35 114.38,85.35 114.49,85.24 114.49,85.11 114.48,85.1 v3(114.49,85.1)
  IN2 w0.127: v3(42.91,71.81) 42.91,71.41 42.81,71.31 42.4,71.31 42.05,71.66 42.05,82.34 48.74,89.02 52.59,89.02 53.5,89.92 55.78,89.92 57.19,91.33 65.35,91.33 65.74,90.94 66.99,90.94 67.96,89.97 76.2,89.97 80.08,93.85 85.61,93.85 87.56,95.8 95.63,95.8 97.51,93.92 98.2,93.92 100.16,91.96 102.42,91.96 104.37,90 106.39,90 108.35,88.04
  BOTTOM w0.102: CL11.2 41.94,71.53 42.13,71.34 42.72,71.34 42.91,71.54 v3(42.91,71.81) ; UC4.AP12 114.04,85.1 114.48,85.1 v3(114.49,85.1)
PCIE_LAN_WAKE#: length 312.9
  TOP w0.102: UB1.19 v2(70.93,29.4) 70.93,30.34 RB27.2 71.76,31.17 71.76,31.99 71.84,32.06 71.84,32.72 70.47,34.1 66.1,34.1 62.19,38.01 60,38.01 59.7,37.7 56.99,37.7 56.53,37.25 55.75,37.25 51.54,33.04 51.54,23 v3(52.94,21.6)
  IN2 w0.127: v3(89.09,15.42) 88.92,15.25 87.23,15.25 86.48,16 84.16,16 83.63,16.52 79.32,16.52 78.35,15.55 77.23,15.55 75.89,14.21 70.01,14.21 69.27,13.47 63.79,13.47 61.79,15.47 58.31,15.47 52.93,20.85 52.93,21.59 v3(52.94,21.6) 52.56,21.98 51.8,21.98 44.51,29.28 43.27,29.28 36.7,35.85 36.7,46.71 46.59,56.6 v3(46.59,60.87)
  BOTTOM w0.102: UL1.21 39.26,68.55 39.81,68 41.94,68 42.25,67.7 42.25,66.43 46.59,62.08 v3(46.59,60.87) ; RM2.1 175.93,88.15 174.53,86.75 174.53,82.3 169.99,77.77 169.99,13.78 163.12,6.91 125.06,6.91 120.68,11.29 114.51,11.29 111.55,14.24 101.27,14.24 100.36,15.15 89.35,15.15 v3(89.09,15.42)
PCIE_PRX_DTX_N0_C: length 4.2
  BOTTOM w0.102: UL1.18 38.11,69.75 38.2,69.84 38.47,69.84 38.83,70.2 38.83,70.46 39.58,71.21 40.07,71.21 v4(40.07,71.2) 40.07,71.21 40.6,71.21 CL12.1
PCIE_PRX_DTX_N1: length 181
  TOP w0.102: CR8.1 46.3,18.83 46.3,19.05 46.16,19.19 45.56,19.19 45.02,18.65 v4(45.02,18.39) 45.02,17.31 44.6,16.89 44.27,16.89 v3(43.99,16.61)
  IN2 w0.089: v3(115.5,86.14) 115.34,85.98 115.1,85.98 114.92,85.79 114.92,83.64 114.66,83.38 114.12,83.38 113.62,83.88 109.86,83.88 109.4,84.33 109.4,85.1 108.97,85.53 108.64,85.53 108.29,85.88 108.29,87.26 107.96,87.58 107.96,87.64
  IN2 w0.127: 107.96,87.64 106.28,89.32 104.16,89.32 102.04,91.44 99.81,91.44 99.14,92.11 98.17,92.11 95.44,94.83 89.18,94.83 88.12,93.77 88.12,91.42 86.6,89.9 86.6,88.02 84.09,85.51 75.17,85.51 74.7,85.99 72.65,85.99 71.61,87.03 47.48,87.03 43.04,82.59 43.04,72.55 43.43,72.16 43.43,70.63 43.07,70.27 41.49,70.27 40.94,69.72 40.94,67.38 38.48,64.93 34.5,64.93 32.35,62.78 32.35,58.33 26.64,52.61 26.64,35.46 28.55,33.55 31.65,33.55 42.39,22.81 42.39,17.6 43.26,16.73 43.87,16.73 v3(43.99,16.61)
  BOTTOM w0.102: v3(115.5,86.14) 115.34,86.14 UC4.AT9
PCIE_PRX_DTX_N1_C: length 2.3
  TOP w0.102: CR8.2 46.32,17.21 46.32,16.26 46.18,16.12 UR1.6
PCIE_PRX_DTX_N3: length 84.5
  IN2 w0.127: v3(114.51,87.03) 114.51,86.89 114.29,86.67 114.11,86.67 113.89,86.9 113.89,89.05 114.28,89.44 114.28,92.31 115.15,93.18 115.15,98.1 115.85,98.81 125.21,98.81 127.42,96.61 140.42,96.61 140.42,96.61 140.86,96.61 146.17,91.29 148.35,91.29 149.11,92.06 162.19,92.06 162.55,91.7 165.68,91.7 167.78,89.61 169.03,89.61 169.37,89.26 v3(169.37,89.19)
  BOTTOM w0.102: v3(114.51,87.03) 114.51,86.93 114.33,86.75 114.18,86.75 114.01,86.92 UC4.AP7 ; JWLAN1.23 160.95,92.52 160.66,92.81 160.66,92.93 160.74,93.01 163.86,93.01 167.23,89.65 169.01,89.65 169.37,89.28 v3(169.37,89.19)
PCIE_PRX_DTX_P0_C: length 4.2
  BOTTOM w0.102: UL1.17 38.14,70.15 38.24,70.06 38.38,70.06 38.62,70.29 38.62,70.54 v4(38.84,70.77) 39.49,71.42 40.65,71.42 CL11.1
PCIE_PRX_DTX_P1: length 181
  TOP w0.102: v3(43.99,17.35) 43.99,17.17 44.05,17.11 44.51,17.11 44.8,17.4 44.8,18.11 44.79,18.12 44.79,18.73 45.47,19.41 46.25,19.41 46.52,19.14 46.52,18.62 46.65,18.49 CR7.1
  IN2 w0.089: 107.77,87.45 107.78,87.44 107.84,87.44 108.1,87.18 108.1,85.8 108.56,85.34 108.89,85.34 109.21,85.02 109.21,84.25 109.78,83.69 113.54,83.69 114.04,83.19 114.74,83.19 115.11,83.56 115.11,85.71 115.18,85.79 115.34,85.79 115.5,85.63 v3(115.5,85.48)
  IN2 w0.127: 107.77,87.45 106.17,89.05 104.05,89.05 101.93,91.17 99.7,91.17 99.03,91.84 98.06,91.84 95.33,94.57 89.29,94.57 88.39,93.66 88.39,91.31 86.86,89.79 86.86,87.91 84.2,85.25 75.06,85.25 74.59,85.72 72.54,85.72 71.5,86.76 47.59,86.76 43.31,82.48 43.31,72.66 43.7,72.27 43.7,70.52 43.18,70 41.6,70 41.21,69.61 41.21,67.27 38.6,64.66 34.61,64.66 32.62,62.67 32.62,58.21 26.91,52.5 26.91,35.57 28.66,33.82 31.76,33.82 42.65,22.92 42.65,17.71 43.37,17 43.83,17 43.99,17.16 v3(43.99,17.35)
  BOTTOM w0.102: UC4.AT10 115.2,85.78 v3(115.5,85.48)
PCIE_PRX_DTX_P1_C: length 2.2
  TOP w0.102: UR1.5 46.68,16.12 46.54,16.26 46.54,17.24 CR7.2
PCIE_PRX_DTX_P3: length 84.6
  IN2 w0.127: v3(169.36,89.87) 167.89,89.87 165.79,91.97 162.66,91.97 162.3,92.32 149,92.32 148.24,91.56 146.28,91.56 140.97,96.87 140.31,96.87 127.53,96.87 125.32,99.08 115.74,99.08 114.88,98.21 114.88,93.29 114.01,92.42 114.01,89.55 113.62,89.16 113.62,86.79 114,86.41 114.44,86.41 v3(114.51,86.34)
  BOTTOM w0.102: v3(169.36,89.87) 169.35,89.86 167.32,89.86 163.95,93.23 160.65,93.23 160.45,93.02 160.45,92.96 160.15,92.66 JWLAN1.25 ; UC4.AP9 114.36,86.49 v3(114.51,86.34)
PCIE_PTX_C_DRX_N1: length 183.9
  TOP w0.102: v3(48.32,17.03) 48.61,17.03 48.77,16.88 48.77,16.64 48.34,16.21 48.34,16.03 48.18,15.86 UR1.2
  IN2 w0.127: v3(48.32,17.03) 48.69,17.03 48.81,16.91 48.81,15.83 48.1,15.12 42.45,15.12 39.78,17.79 39.78,21.55 30.69,30.64 28.35,30.64 27.62,31.38 27.62,32.44 25.34,34.72 25.34,53.13 30.88,58.67 30.88,64.6 32.14,65.86 32.14,70.24 32.77,70.87 38.59,70.87 39.52,71.8 39.52,83.48 49.07,93.04 73.15,93.04 73.26,92.92 v3(73.26,92.48)
  BOTTOM w0.102: v3(73.26,92.48) 73.26,92.82 73.46,93.02 76.87,93.02 79.37,95.53 85.97,95.53 89.91,99.46 114.24,99.46 115.04,98.66 117.74,98.66 117.93,98.47 117.93,97.93 117.83,97.82 CC7.2
PCIE_PTX_C_DRX_N3: length 73.1
  IN2 w0.127: v3(115.81,97.34) 116.02,97.55 116.02,97.88 116.42,98.28 123.32,98.28 125.83,95.78 140.48,95.78 145.47,90.79 148.56,90.79 149.32,91.55 161.91,91.55 162.26,91.19 165.45,91.19 168.1,88.54 168.29,88.54 v3(168.46,88.71)
  BOTTOM w0.102: v3(115.81,97.34) 116.08,97.06 116.08,96.53 CC11.2 ; v3(168.46,88.71) 168.28,88.53 158.69,88.53 157.46,89.76 157.46,90.34 157.75,90.63 JWLAN1.31
PCIE_PTX_C_DRX_P1: length 183.9
  TOP w0.102: v3(49.23,17.02) 48.98,16.77 48.98,16.55 48.56,16.13 48.56,16 48.68,15.88 UR1.1
  IN2 w0.127: v3(73.31,93.47) 73.14,93.3 48.96,93.3 39.25,83.59 39.25,71.91 38.48,71.14 32.66,71.14 31.87,70.35 31.87,65.97 30.61,64.71 30.61,58.78 25.08,53.24 25.08,34.61 27.35,32.33 27.35,31.27 28.24,30.37 30.58,30.37 39.52,21.44 39.52,17.68 42.34,14.85 48.21,14.85 49.08,15.72 49.08,16.86 v3(49.23,17.02)
  BOTTOM w0.102: CC6.2 118.15,98.07 118.15,98.56 117.83,98.87 115.13,98.87 114.33,99.67 89.82,99.67 85.88,95.74 79.28,95.74 76.78,93.24 73.55,93.24 v3(73.31,93.47)
PCIE_PTX_C_DRX_P3: length 73.3
  IN2 w0.127: v3(116.58,97.34) 116.42,97.34 116.28,97.47 116.28,97.77 116.53,98.01 123.21,98.01 125.72,95.51 140.37,95.51 145.36,90.52 148.67,90.52 149.43,91.28 161.8,91.28 162.15,90.93 165.34,90.93 167.99,88.27 168.31,88.27 v3(168.46,88.13)
  BOTTOM w0.102: JWLAN1.33 156.95,90.63 157.24,90.34 157.24,89.67 158.6,88.31 168.28,88.31 v3(168.46,88.13) ; v3(116.58,97.34) 116.41,97.34 116.3,97.23 116.3,96.49 CC10.2
PCIE_PTX_DRX_N1: length 10.8
  IN2 w0.089: v3(115.57,88.89) 115.57,88.77 115.7,88.63 115.92,88.63 116,88.71 116,89.89 115.96,89.92
  IN2 w0.127: v3(117.55,95.85) 117.83,95.85 117.93,95.75 117.93,93.6 116.34,92.01 116.34,90.86 115.96,90.48 115.96,89.92
  BOTTOM w0.102: UC4.AV4 115.87,88.59 v3(115.57,88.89) ; CC7.1 117.84,96.58 117.84,96.14 v3(117.55,95.85)
PCIE_PTX_DRX_N2: length 8.9
  IN2 w0.089: 116.95,89.34 116.94,89.32 116.94,89.27 116.68,89.02 116.68,88.03 115.93,87.28 115.83,87.28 v3(115.53,87.58)
  IN2 w0.127: 116.95,89.34 117.31,89.7 117.31,90.65 117.81,91.16 117.81,91.74 117.69,91.86 v3(117.49,91.86)
  BOTTOM w0.102: v3(117.49,91.86) 117.68,91.86 117.83,92.01 117.83,93.03 CC9.1 ; UC4.AT6 115.2,87.91 v3(115.53,87.58)
PCIE_PTX_DRX_N3: length 9.2
  IN2 w0.089: 114.87,88.71 114.87,88.69 114.9,88.66 114.9,88.16 114.82,88.07 114.59,88.07 114.48,88.17 v3(114.48,88.3)
  IN2 w0.127: 114.87,88.71 114.87,92.06 115.97,93.16 115.97,93.37 v3(115.67,93.67)
  BOTTOM w0.102: v3(115.67,93.67) 116.1,94.1 116.1,94.89 CC11.1 ; v3(114.48,88.3) 114.19,88.59 UC4.AP4
PCIE_PTX_DRX_P1: length 10.8
  IN2 w0.089: v3(115.57,88.22) 115.78,88.44 116,88.44 116.19,88.63 116.19,89.88 116.23,89.91 116.23,89.92
  IN2 w0.127: v3(118.36,95.87) 118.19,95.71 118.19,93.48 116.61,91.9 116.61,90.75 116.23,90.37 116.23,89.92
  BOTTOM w0.102: v3(118.36,95.87) 118.05,96.18 118.05,96.56 CC6.1 ; v3(115.57,88.22) 115.87,87.91 UC4.AV6
PCIE_PTX_DRX_P2: length 8.9
  IN2 w0.089: 117.14,89.15 117.12,89.13 117.07,89.13 116.87,88.94 116.87,87.95 116.01,87.09 115.8,87.09 v3(115.53,86.82)
  IN2 w0.127: v3(118.25,91.86) 118.08,91.69 118.08,91.05 117.58,90.54 117.58,89.59 117.14,89.15
  BOTTOM w0.102: v3(118.25,91.86) 118.05,92.06 118.05,93.13 CC8.1 ; v3(115.53,86.82) 115.15,87.2 UC4.AT7
PCIE_PTX_DRX_P3: length 9.2
  IN2 w0.089: v3(114.51,87.69) 114.7,87.88 114.89,87.88 115.1,88.08 115.1,88.66 115.13,88.69 115.13,88.71
  IN2 w0.127: 115.13,88.71 115.13,91.95 116.24,93.05 116.24,93.49 v3(116.42,93.67)
  BOTTOM w0.102: v3(116.42,93.67) 116.31,93.78 116.31,94.95 CC10.1 ; UC4.AP6 114.28,87.91 v3(114.51,87.69)
PCIE_RCOMPN: length 2.8
  TOP w0.254: RC18.2 113.98,83.81 113.67,84.11 v2(113.67,84.36) 113.85,84.54 114.45,84.54 v3(114.51,84.49)
  BOTTOM w0.254: UC4.AP13 114.14,84.49 v3(114.51,84.49)
PCIE_RCOMPP: length 2.7
  TOP w0.254: v3(114.48,83.87) 114.6,83.87 114.87,84.13 v2(115.27,84.13) 115.4,84.01 115.4,83.55 115.07,83.22 RC18.1
  BOTTOM w0.254: v3(114.48,83.87) 114.24,83.87 UC4.AP14
PCU_SMB_ALERT#: length 6.7
  BOTTOM w0.102: UC4.BG11 120.87,85.07 121.17,85.07 121.31,84.94 121.31,84.94 121.32,84.93 122.29,84.93 123.02,85.66 123.48,85.66 124.24,86.42 v2(125,86.42) 125.77,86.42 126.09,86.74 RPC9.2
PCU_SMB_CLK: length 19.2
  TOP w0.102: v3(126.98,88.27) 126.98,88.35 127.41,88.78 127.8,88.78 128.33,88.25 128.33,86.75 131.15,83.93 132.29,83.93 132.88,84.51 133.96,84.51 135.17,83.3 QC4.3
  BOTTOM w0.102: UC4.BH10 121.18,85.81 121.55,85.81 121.95,86.21 123.19,86.21 124.09,87.1 125.29,87.1 125.93,87.74 RPC9.4 126.98,88.19 v3(126.98,88.27)
PCU_SMB_DATA: length 16.9
  TOP w0.102: QC5.3 130.73,83.3 130.29,83.74 v2(130.29,83.83) 130.29,84.35 128.02,86.62 128.02,88.12 127.8,88.34 v3(127.59,88.34)
  BOTTOM w0.102: 127.59,88.34 127.59,88.34 127.59,88.37 127.59,88.37 v3(127.59,88.34) ; 127.59,88.34 127.59,88.37 127.59,88.34 ; 127.59,88.34 127.62,88.34 127.62,88.32 127.03,87.74 127.03,87.49 126.78,87.24 RPC9.3 125.86,87.24 125.42,86.8 124.21,86.8 123.31,85.89 122.09,85.89 121.7,85.5 121.31,85.5 121.28,85.47 121.27,85.47 121.21,85.41 120.95,85.41 120.84,85.52 120.58,85.52 120.43,85.37 120.43,84.79 UC4.BG12
PHASE1: length 10.6
  IN2 w0.762: 155.66,75.59 155.91,75.34 155.91,72.27 153.32,69.68 153.32,66.7 153.73,66.29
  vias: v2(157.14,76.08) v3(149.59,76.21) v3(150.68,76.26) v3(150.74,75.4) v3(150.74,74.58) v3(151.64,76.24) v3(151.63,74.61) v3(151.68,75.45) v3(152.64,74.61) v3(152.66,76.24) v3(152.67,75.47) v3(153.97,65.57) v3(154.16,76.13) v3(154.47,65.14) v3(154.9,76.13)
PHASEG: length 20.3
  IN2 w0.762: 156.02,81.53 159.49,81.53 160.56,80.46 160.56,67.72 158.75,65.9
  vias: v2(155.43,83.68) v3(151.39,83.84) v3(151.39,83.23) v3(151.42,82.62) v3(151.39,82.01) v3(151.39,81.37) v3(152.05,83.82) v3(152.05,83.21) v3(152.08,82.6) v3(152.71,83.82) v3(152.71,83.21) v3(152.74,82.6) v3(153.4,83.82) v3(153.4,83.21) v3(153.43,82.6) v3(154.03,83.83) v3(154.03,83.22) v3(154.09,82.6) v3(154.72,83.83) v3(154.69,83.22) v3(154.77,82.63) v3(154.94,81.94) v3(154.96,81.3) v3(157.94,64.7) v3(158.42,65.17)
PLT_RST_BUF#: length 413.5
  TOP w0.102: v3(47.05,63.92) 46.74,64.22 46.74,67.8 47.12,68.18 47.12,70.87 51.75,75.5 51.75,78.51 53.28,80.04 54.26,80.04 55.28,79.02 55.94,79.02 56.65,79.74 62.05,79.74 63.28,78.5 63.28,71.77 64.3,70.76 65.44,70.76 66.16,70.04 68.2,70.04 68.29,69.95 69.29,69.95 69.65,70.32 69.65,71.03 70.11,71.48 71,71.48 71.85,70.63 73.71,70.63 74.25,71.18 74.25,80.5 75.97,82.22 UC8.4 ; v3(168.67,86.13) 168.27,86.13 164.37,90.03 164.37,90.59 RC25.2 162.93,90.66 162.93,90.66 162.67,90.41 RM6.2 ; QC2.1 88.58,27.04 88.58,21.36 89.77,20.18 89.77,17.79 90.28,17.28 90.28,14 93.05,11.24 95.08,11.24 96.6,9.71 v3(96.6,9.03) ; QC2.1 89.82,31.38 v3(89.75,31.45) ; QC2.1 90.89,28.28 91.07,28.1 UW1.16 ; v3(111.18,17.53) 111.18,23.71 v3(105.57,29.33) ; UR1.23 v3(50.35,14.23) ; RB29.1 72.24,33.08 72.04,33.28 v3(72.04,33.73)
  IN2 w0.127: v3(72.04,33.73) 67.57,33.73 64.64,36.66 64.64,41.35 64.16,41.84 64.16,44.85 62.77,46.24 62.77,55.61 57.94,60.44 57.94,60.97 57.05,61.85 v3(56.42,61.85)
  BOTTOM w0.102: v3(105.57,29.33) 104.04,29.33 103.49,29.88 101.94,29.88 101.56,30.26 93.76,30.26 92.57,31.45 v3(89.75,31.45) 89.19,30.9 88.25,30.9 87.76,31.38 84.94,31.38 82.18,34.14 73.24,34.14 72.83,33.73 v3(72.04,33.73) ; UL1.19 38.57,69.35 38.61,69.39 38.61,69.4 38.83,69.62 38.83,69.62 39.32,70.11 41.94,70.11 43.47,68.58 43.47,66.23 45.78,63.92 v3(47.05,63.92) 50.43,63.92 53.6,60.74 55.31,60.74 v3(56.42,61.85) ; v3(50.35,14.23) 50.71,13.87 50.71,12.9 50.71,12.9 50.71,12.56 50.71,12.56 50.71,11.95 48.42,9.66 48.42,7.37 48.98,6.81 62.34,6.81 64.01,5.14 69.53,5.14 72.32,7.93 80.45,7.93 81.74,9.23 83.09,9.23 83.6,9.74 93.4,9.74 94.22,8.92 95.03,8.92 95.49,9.38 96.25,9.38 v3(96.6,9.03) ; v3(111.18,17.53) 111.67,17.05 114.36,17.05 115.91,15.5 v2(117.08,15.5) 119.96,15.5 126.67,8.79 161.68,8.79 162.34,8.79 167.17,13.62 167.17,13.92 167.38,14.14 167.38,81.05 166.25,82.18 166.25,83.71 v3(168.67,86.13)
PLT_RST_BUF#_R: length 6
  TOP w0.102: RB30.2 72.8,31.4 72.24,30.84 RB29.2 73.24,30.71 CB10.2 73.33,30.62 v2(73.33,29.55) 73.33,29.54 UB1.13
PLUG_IN: length 3.9
  TOP w0.203: JHP1.6 12.22,20.48 v2(12.71,20.48) 13.16,20.48 RA16.2
PLUG_IN_R: length 12.4
  TOP w0.203: UA1.13 21.22,26.68 19.65,28.25 v2(18.68,28.25) 18.24,28.25 16.16,26.17 16.16,25.1 13.96,22.89 RA15.1 RA16.1
PMC_ACIN: length 18.2
  TOP w0.102: RC26.2 87.78,80.93 ; 87.78,80.93 87.79,80.93 88.3,80.42 88.3,78.62 88.55,78.36 94.98,78.36 95.21,78.59 95.21,79.46 95.68,79.93 v2(96.64,79.93) 96.91,80.19 98.36,80.19 CC14.1 99.3,79.71 v3(99.87,80.28) ; 87.78,80.93 86.58,80.93 DC1.2
  BOTTOM w0.102: v3(99.87,80.28) 99.51,80.64 UC4.D20
PMC_BATLOW#: length 4.7
  TOP w0.102: RPC5.2 99.28,77.61 99.6,77.94 v2(99.8,77.94) 101.5,77.94 v3(101.97,78.4)
  BOTTOM w0.102: v3(101.97,78.4) 102.32,78.05 UC4.K26
PMC_CORE_PWROK: length 121.9
  TOP w0.102: v3(66.71,25.15) 66.71,25.46 65.73,26.44 UB1.32
  IN2 w0.127: v3(66.71,25.15) 66.71,26.72 61.7,31.72 61.7,36.35 v3(61.88,36.53)
  BOTTOM w0.102: UC4.B7 97.97,86.85 97.7,86.85 96.39,88.16 96.39,90.17 96.02,90.54 96.02,94.13 95.79,94.35 UC9.2 93.17,94.35 92.42,95.1 92.42,95.72 92.12,96.02 v2(91.07,96.02) 90.58,96.02 89.26,94.7 89.26,91.45 87.76,89.95 87.76,88.1 84.35,84.68 79.36,84.68 78.52,85.53 76.27,85.53 76.09,85.71 69.99,85.71 68.45,84.17 67.98,84.17 67.46,83.65 66.54,83.65 64.53,81.65 64.53,77.22 63.51,76.2 63.51,72.35 66.67,69.2 66.93,69.2 67.66,68.47 67.66,59.24 59.36,50.95 59.36,47.02 57.23,44.89 57.23,40.63 61.34,36.52 61.87,36.52 61.87,36.53 v3(61.88,36.53)
